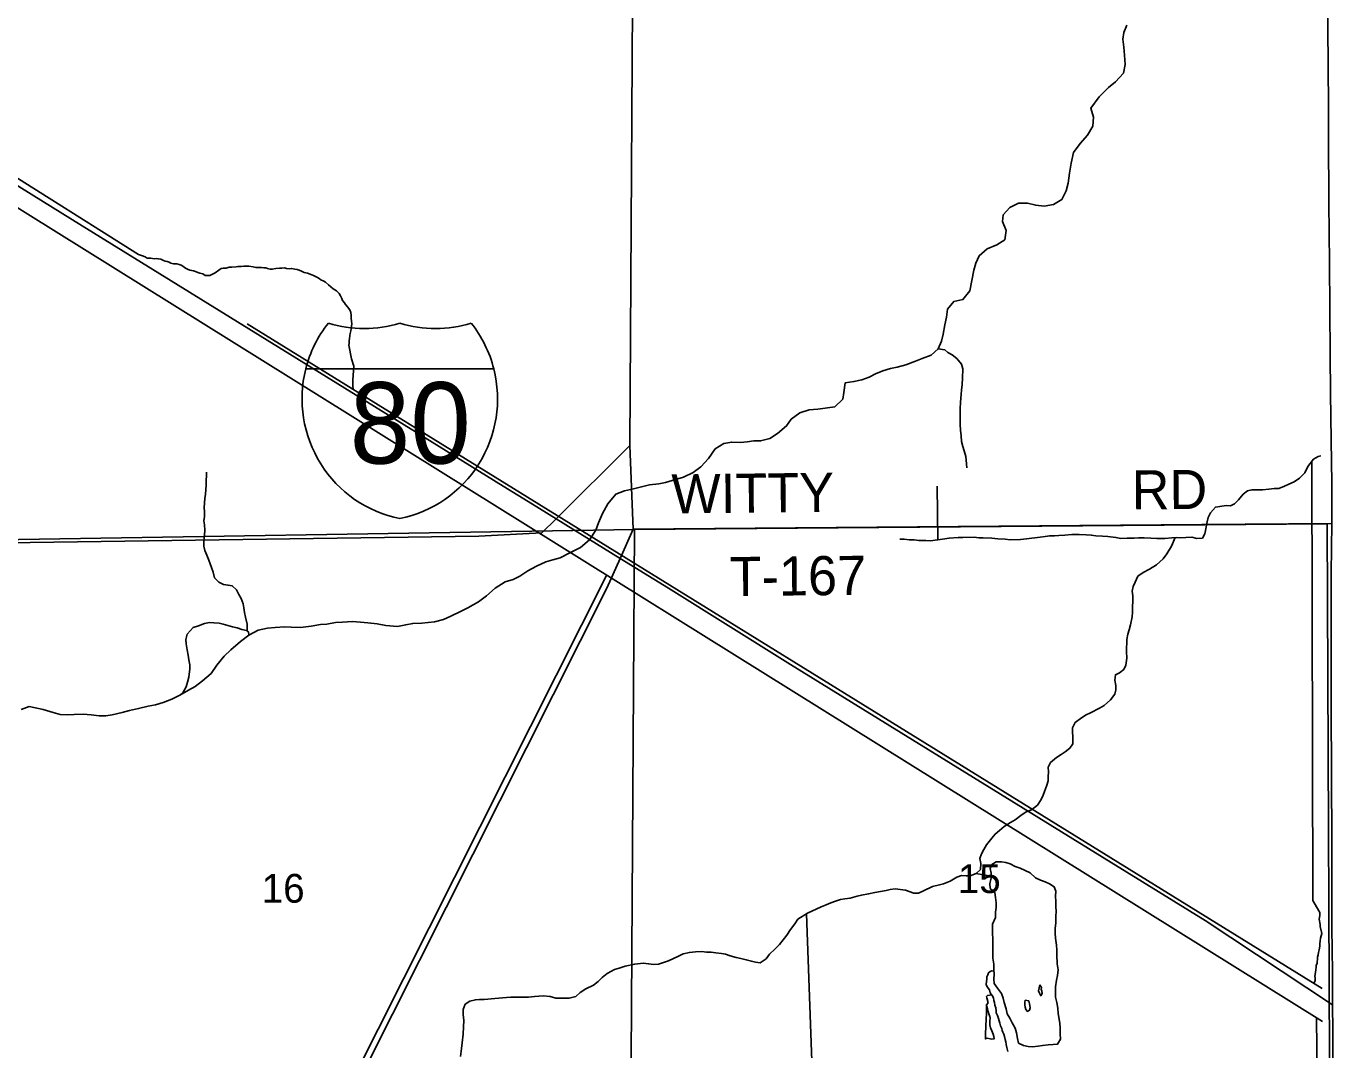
# Model space of a CAD drawing. Extents: x 1588073 to 2013523, y 1090242 to 1357120.
# Drawn here: x 1728558 to 1738590, y 1267246 to 1275104 of the extents above; entities that cross this region are included whole.
import ezdxf

# ---------------------------------------------------------------- set-up
doc = ezdxf.new("R2010")
doc.units = 0
for name, color, linetype in [('GM_X_Adjacent_County', 7, 'Continuous'), ('GM_X_County', 7, 'Continuous'), ('GM_X_County_Road', 7, 'Continuous'), ('GM_X_Interstate_Location', 7, 'Continuous'), ('GM_X_Interstate_Route', 7, 'Continuous'), ('GM_X_Interstate_Shield', 7, 'Continuous'), ('GM_X_Major_River', 7, 'Continuous'), ('GM_X_Minor_Lake', 7, 'Continuous'), ('GM_X_Minor_River', 7, 'Continuous'), ('GM_X_Section', 7, 'Continuous'), ('GM_X_Section_Text', 7, 'Continuous'), ('GM_X_Township', 7, 'Continuous'), ('GM_X_Township_Road', 7, 'Continuous'), ('GM_X_Township_Road_Text', 7, 'Continuous')]:
    doc.layers.add(name, color=color, linetype=linetype)

msp = doc.modelspace()

# ---------------------------------------------------------------- linework, layer by layer
at = {"layer": 'GM_X_Adjacent_County'}
msp.add_lwpolyline([(1738550, 1275274), (1738551, 1275094), (1738555, 1274798), (1738556, 1274485), (1738557, 1274256), (1738559, 1273747), (1738563, 1273288), (1738570, 1272581), (1738571, 1272286), (1738576, 1271925), (1738583, 1271596), (1738583, 1271286), (1738578, 1270907), (1738576, 1270281), (1738577, 1269874), (1738581, 1268839), (1738583, 1268494), (1738583, 1268182), (1738587, 1267846), (1738587, 1267761), (1738587, 1267676), (1738587, 1267593), (1738589, 1267394), (1738590, 1267179)], dxfattribs=at)
at = {"layer": 'GM_X_County'}
msp.add_lwpolyline([(1738550, 1275274), (1738551, 1275094), (1738555, 1274798), (1738556, 1274485), (1738557, 1274256), (1738559, 1273747), (1738563, 1273288), (1738570, 1272581), (1738571, 1272286), (1738576, 1271925), (1738583, 1271596), (1738583, 1271286), (1738578, 1270907), (1738576, 1270281), (1738577, 1269874), (1738581, 1268839), (1738583, 1268494), (1738583, 1268182), (1738587, 1267846), (1738587, 1267761), (1738587, 1267676), (1738587, 1267593), (1738589, 1267394), (1738590, 1267179)], dxfattribs=at)
at = {"layer": 'GM_X_County_Road'}
for points in [[(1738583, 1271286), (1738583, 1271596), (1738576, 1271925), (1738571, 1272286), (1738570, 1272581), (1738563, 1273288), (1738559, 1273747), (1738557, 1274256), (1738556, 1274485), (1738555, 1274798), (1738551, 1275094), (1738550, 1275274), (1738545, 1275652), (1738544, 1275816), (1738542, 1275964), (1738541, 1276144), (1738537, 1276358), (1738534, 1276572), (1738534, 1276592)], [(1730572, 1262010), (1730565, 1263302), (1730549, 1265887), (1733017, 1270791), (1733118, 1271018), (1733219, 1271243), (1733193, 1271885), (1733222, 1276540)], [(1738590, 1267179), (1738589, 1267394), (1738587, 1267593), (1738587, 1267676), (1738587, 1267761), (1738587, 1267846), (1738583, 1268182), (1738583, 1268494), (1738581, 1268839), (1738577, 1269874), (1738576, 1270281), (1738578, 1270907), (1738583, 1271286)]]:
    msp.add_lwpolyline(points, dxfattribs=at)
at = {"layer": 'GM_X_Interstate_Route'}
msp.add_lwpolyline([(1724225, 1276479), (1725529, 1275710), (1726922, 1274850), (1727192, 1274684), (1727551, 1274461), (1727819, 1274295), (1727885, 1274253), (1728987, 1273572), (1731547, 1271991), (1732220, 1271572), (1732446, 1271435), (1732627, 1271323), (1733118, 1271018), (1733490, 1270790), (1734426, 1270205), (1736889, 1268684), (1737609, 1268240), (1738587, 1267593)], dxfattribs=at)
at = {"layer": 'GM_X_Interstate_Shield'}
for p, q in [((1730706, 1272473), (1732148, 1272473)), ((1732148, 1272473), (1730706, 1272473)), ((1732148, 1272473), (1730706, 1272473))]:
    msp.add_line(p, q, dxfattribs=at)
for centre, start, end in [((1731614, 1272243), 141.669, 165.8066), ((1731153, 1273721), 253.0091, 286.9909), ((1731701, 1273721), 253.0091, 286.9909), ((1731239, 1272243), 14.1934, 38.331), ((1731614, 1272243), 165.8066, 258.463), ((1731239, 1272243), 281.537, 14.1934)]:
    msp.add_arc(centre, 938, start, end, dxfattribs=at)
at = {"layer": 'GM_X_Major_River'}
for points in [[(1737009, 1275112), (1736984, 1275054), (1736978, 1275004), (1736984, 1274942), (1736991, 1274882), (1736995, 1274810), (1736982, 1274742), (1736920, 1274676), (1736868, 1274634), (1736797, 1274560), (1736732, 1274474), (1736752, 1274404), (1736746, 1274336), (1736705, 1274268), (1736649, 1274202), (1736598, 1274133), (1736580, 1274052), (1736567, 1273974), (1736557, 1273898), (1736542, 1273840), (1736510, 1273772), (1736445, 1273735), (1736373, 1273723), (1736309, 1273729), (1736245, 1273746), (1736177, 1273746), (1736111, 1273712), (1736058, 1273655), (1736054, 1273605), (1736082, 1273534), (1736071, 1273464), (1736011, 1273424), (1735937, 1273395), (1735874, 1273341), (1735850, 1273285), (1735833, 1273231), (1735819, 1273151), (1735802, 1273073), (1735750, 1273005), (1735680, 1272989), (1735631, 1272932), (1735625, 1272869), (1735610, 1272811), (1735598, 1272739), (1735586, 1272687), (1735559, 1272627), (1735505, 1272578), (1735437, 1272554), (1735386, 1272532), (1735312, 1272505), (1735246, 1272487), (1735194, 1272475), (1735136, 1272457), (1735079, 1272434), (1735029, 1272410), (1734975, 1272388), (1734913, 1272375), (1734847, 1272367), (1734836, 1272293), (1734828, 1272241), (1734767, 1272183), (1734637, 1272164), (1734569, 1272158), (1734499, 1272137), (1734432, 1272087), (1734396, 1272035), (1734327, 1271977), (1734267, 1271939), (1734197, 1271920), (1734145, 1271920), (1734093, 1271914), (1734043, 1271907), (1733975, 1271911), (1733914, 1271900), (1733848, 1271860), (1733797, 1271786), (1733737, 1271722), (1733679, 1271678), (1733604, 1271641), (1733544, 1271623)], [(1733544, 1271623), (1733466, 1271600), (1733414, 1271592), (1733344, 1271582), (1733293, 1271570), (1733221, 1271553), (1733151, 1271537), (1733085, 1271512), (1733024, 1271438), (1732982, 1271362), (1732953, 1271292), (1732931, 1271236), (1732882, 1271162), (1732814, 1271102), (1732733, 1271061), (1732657, 1271023), (1732601, 1271007), (1732547, 1270992), (1732476, 1270960), (1732410, 1270924), (1732348, 1270883), (1732296, 1270857), (1732235, 1270839), (1732159, 1270789), (1732093, 1270730), (1732030, 1270686), (1731950, 1270640), (1731898, 1270613), (1731819, 1270575), (1731761, 1270549), (1731693, 1270532), (1731597, 1270522), (1731526, 1270519), (1731472, 1270509), (1731410, 1270497), (1731320, 1270504), (1731254, 1270516), (1731180, 1270525), (1731126, 1270529), (1731064, 1270533), (1730986, 1270530), (1730932, 1270526), (1730867, 1270515), (1730817, 1270511), (1730747, 1270499), (1730665, 1270488), (1730593, 1270492), (1730543, 1270494), (1730471, 1270489), (1730411, 1270483), (1730338, 1270468), (1730268, 1270430), (1730204, 1270380), (1730129, 1270318), (1730079, 1270267), (1730022, 1270199), (1729978, 1270135), (1729913, 1270079), (1729855, 1270035), (1729805, 1270006), (1729739, 1269970), (1729676, 1269938), (1729610, 1269913), (1729550, 1269895), (1729496, 1269885), (1729421, 1269866), (1729351, 1269850), (1729295, 1269836), (1729219, 1269819), (1729169, 1269811), (1729119, 1269811), (1729057, 1269818), (1728997, 1269822), (1728926, 1269820), (1728876, 1269817), (1728820, 1269821), (1728766, 1269835), (1728688, 1269858), (1728581, 1269881)], [(1728581, 1269881), (1728521, 1269860)], [(1736331, 1267699), (1736337, 1267682), (1736347, 1267662), (1736357, 1267680), (1736355, 1267698), (1736351, 1267712), (1736352, 1267726), (1736340, 1267746)], [(1736340, 1267746), (1736331, 1267699)], [(1736228, 1267627), (1736226, 1267612), (1736225, 1267593), (1736227, 1267575), (1736233, 1267557), (1736245, 1267541), (1736261, 1267551), (1736265, 1267569), (1736263, 1267587), (1736256, 1267623)], [(1736256, 1267623), (1736228, 1267627)]]:
    msp.add_lwpolyline(points, dxfattribs=at)
at = {"layer": 'GM_X_Minor_Lake'}
for points in [[(1735972, 1268669), (1735959, 1268638), (1735966, 1268603), (1735967, 1268565), (1735957, 1268523), (1735960, 1268485), (1735994, 1268455), (1736001, 1268416), (1736005, 1268376), (1736004, 1268340), (1736000, 1268304), (1735999, 1268262), (1735978, 1268210), (1735977, 1268138), (1735979, 1268102), (1735980, 1268038), (1735979, 1267994), (1735980, 1267950), (1735988, 1267904), (1735987, 1267862), (1735989, 1267825), (1735988, 1267791), (1735990, 1267755), (1736015, 1267721), (1736046, 1267678), (1736060, 1267644), (1736067, 1267610), (1736081, 1267562), (1736090, 1267523), (1736110, 1267489), (1736127, 1267453), (1736151, 1267412), (1736162, 1267376), (1736169, 1267334), (1736177, 1267298), (1736215, 1267279), (1736251, 1267272), (1736285, 1267270), (1736327, 1267275), (1736361, 1267279), (1736405, 1267284), (1736443, 1267288), (1736477, 1267291), (1736498, 1267329), (1736496, 1267369), (1736497, 1267415), (1736494, 1267449), (1736488, 1267483), (1736481, 1267526), (1736479, 1267566), (1736470, 1267610), (1736461, 1267650), (1736461, 1267690), (1736460, 1267730), (1736468, 1267782), (1736477, 1267818), (1736480, 1267860), (1736474, 1267908), (1736471, 1267977), (1736470, 1268015), (1736468, 1268051), (1736461, 1268103), (1736458, 1268141), (1736458, 1268179), (1736463, 1268221), (1736464, 1268273), (1736466, 1268309), (1736463, 1268348), (1736463, 1268384), (1736460, 1268426), (1736463, 1268464), (1736451, 1268498), (1736415, 1268521), (1736382, 1268535), (1736346, 1268550), (1736306, 1268566), (1736266, 1268605), (1736227, 1268624), (1736189, 1268640), (1736151, 1268653), (1736113, 1268673), (1736079, 1268684), (1736047, 1268690)], [(1736047, 1268690), (1736043, 1268690), (1736005, 1268689), (1735972, 1268669)], [(1735931, 1267594), (1735930, 1267542), (1735930, 1267512), (1735928, 1267496), (1735927, 1267462), (1735925, 1267448), (1735923, 1267345), (1735923, 1267331), (1735937, 1267335), (1735959, 1267331), (1735973, 1267329), (1735989, 1267330), (1735987, 1267348)], [(1735931, 1267594), (1735930, 1267542), (1735930, 1267512), (1735928, 1267496), (1735927, 1267462), (1735925, 1267448), (1735923, 1267345), (1735923, 1267331), (1735937, 1267335), (1735959, 1267331), (1735973, 1267329), (1735989, 1267330), (1735987, 1267348), (1735982, 1267367), (1735972, 1267393), (1735962, 1267415), (1735957, 1267439), (1735957, 1267469), (1735960, 1267489), (1735956, 1267503), (1735950, 1267523), (1735944, 1267542), (1735939, 1267562), (1735933, 1267580), (1735931, 1267594)], [(1735987, 1267348), (1735982, 1267367), (1735972, 1267393), (1735962, 1267415), (1735957, 1267439), (1735957, 1267469), (1735960, 1267489), (1735956, 1267503), (1735950, 1267523), (1735944, 1267542), (1735939, 1267562), (1735933, 1267580), (1735931, 1267594)]]:
    msp.add_lwpolyline(points, dxfattribs=at)
at = {"layer": 'GM_X_Minor_River'}
for p, q in [((1724253, 1276352), (1738510, 1267465)), ((1724641, 1276356), (1729421, 1273352)), ((1730256, 1272820), (1738508, 1267717)), ((1738428, 1271763), (1738437, 1268394)), ((1735552, 1271572), (1735558, 1271162)), ((1733015, 1270892), (1730501, 1265898)), ((1735848, 1268600), (1735966, 1268579)), ((1734549, 1268291), (1734632, 1265984)), ((1738448, 1267755), (1738448, 1267755)), ((1735932, 1267657), (1735939, 1267663)), ((1735933, 1267647), (1735932, 1267657)), ((1735932, 1267657), (1735932, 1267657)), ((1735939, 1267663), (1735971, 1267668)), ((1735939, 1267663), (1735939, 1267663)), ((1735931, 1267591), (1735943, 1267607)), ((1735943, 1267607), (1735933, 1267647)), ((1735933, 1267647), (1735933, 1267647)), ((1735943, 1267607), (1735943, 1267607)), ((1738464, 1267494), (1738525, 1261851))]:
    msp.add_line(p, q, dxfattribs=at)
for points in [[(1729421, 1273352), (1729452, 1273341), (1729472, 1273332), (1729486, 1273324), (1729500, 1273324), (1729514, 1273322), (1729540, 1273319), (1729556, 1273321), (1729574, 1273317), (1729592, 1273315), (1729612, 1273306), (1729626, 1273300), (1729640, 1273298), (1729656, 1273292), (1729670, 1273285), (1729690, 1273279), (1729716, 1273279), (1729732, 1273274), (1729748, 1273268), (1729762, 1273262), (1729781, 1273246), (1729797, 1273239), (1729815, 1273231), (1729829, 1273227), (1729843, 1273225), (1729859, 1273220), (1729877, 1273214), (1729891, 1273208), (1729915, 1273202), (1729933, 1273191), (1729953, 1273189), (1729969, 1273189), (1729993, 1273202), (1730009, 1273210), (1730037, 1273230), (1730054, 1273244), (1730070, 1273245), (1730094, 1273247), (1730116, 1273253), (1730136, 1273254), (1730170, 1273256), (1730184, 1273258), (1730210, 1273259), (1730230, 1273261), (1730250, 1273261), (1730268, 1273261), (1730300, 1273256), (1730322, 1273252), (1730366, 1273251), (1730384, 1273249), (1730398, 1273249), (1730412, 1273244), (1730432, 1273238), (1730448, 1273238), (1730474, 1273243), (1730502, 1273247), (1730522, 1273247), (1730542, 1273248), (1730556, 1273244), (1730578, 1273242), (1730596, 1273244), (1730620, 1273239), (1730638, 1273235), (1730654, 1273231), (1730672, 1273223), (1730692, 1273214), (1730718, 1273208), (1730750, 1273195), (1730764, 1273189), (1730780, 1273181), (1730794, 1273175), (1730807, 1273166), (1730821, 1273156), (1730843, 1273146), (1730857, 1273138), (1730879, 1273117), (1730914, 1273087), (1730940, 1273072), (1730960, 1273052), (1730972, 1273034), (1730981, 1273014), (1730987, 1272999), (1731003, 1272981), (1731011, 1272967), (1731025, 1272949), (1731042, 1272926), (1731050, 1272906), (1731052, 1272882), (1731053, 1272862), (1731057, 1272840), (1731059, 1272818), (1731056, 1272800), (1731052, 1272780), (1731050, 1272766), (1731046, 1272744), (1731043, 1272730), (1731041, 1272704), (1731039, 1272690), (1731038, 1272668), (1731036, 1272654), (1731055, 1272551)], [(1735559, 1272627), (1735610, 1272619), (1735633, 1272600), (1735667, 1272582), (1735703, 1272553), (1735738, 1272509), (1735748, 1272473), (1735747, 1272401), (1735745, 1272354), (1735740, 1272310), (1735736, 1272278), (1735731, 1272214), (1735729, 1272170), (1735728, 1272112), (1735728, 1272078), (1735729, 1272046), (1735731, 1272002), (1735737, 1271958), (1735740, 1271916), (1735748, 1271877), (1735759, 1271845), (1735771, 1271801), (1735778, 1271745), (1735780, 1271713)], [(1731055, 1272551), (1731074, 1272493), (1731066, 1272389), (1731066, 1272336), (1731072, 1272315)], [(1738498, 1271805), (1738477, 1271801), (1738441, 1271780), (1738398, 1271724), (1738374, 1271674), (1738333, 1271634), (1738293, 1271607), (1738253, 1271587), (1738218, 1271573), (1738176, 1271556), (1738140, 1271554), (1738098, 1271551), (1738050, 1271545), (1738006, 1271544), (1737968, 1271544), (1737934, 1271536), (1737902, 1271511), (1737865, 1271469), (1737835, 1271437), (1737803, 1271423), (1737771, 1271424), (1737722, 1271418), (1737688, 1271413), (1737650, 1271367), (1737632, 1271333), (1737625, 1271299), (1737606, 1271207), (1737588, 1271173), (1737546, 1271170), (1737508, 1271182), (1737460, 1271180), (1737424, 1271177), (1737388, 1271179), (1737354, 1271177), (1737300, 1271170), (1737238, 1271171), (1737192, 1271173), (1737140, 1271176), (1737099, 1271176), (1737065, 1271174), (1737011, 1271173), (1736963, 1271171), (1736925, 1271180), (1736863, 1271187), (1736821, 1271189), (1736769, 1271192), (1736735, 1271198), (1736695, 1271200), (1736641, 1271203), (1736585, 1271201), (1736533, 1271198), (1736487, 1271194), (1736453, 1271193), (1736417, 1271193), (1736381, 1271187), (1736343, 1271182), (1736239, 1271169), (1736191, 1271163), (1736113, 1271162), (1736075, 1271165), (1736017, 1271169), (1735971, 1271174), (1735905, 1271176), (1735873, 1271177), (1735835, 1271181), (1735748, 1271180), (1735714, 1271178), (1735644, 1271175), (1735592, 1271165), (1735502, 1271154), (1735464, 1271157), (1735412, 1271157), (1735376, 1271162), (1735338, 1271162), (1735300, 1271166), (1735266, 1271165)], [(1730256, 1270463), (1730255, 1270513), (1730242, 1270567), (1730234, 1270603), (1730229, 1270639), (1730225, 1270671), (1730209, 1270710), (1730192, 1270742), (1730174, 1270778), (1730140, 1270808), (1730108, 1270813), (1730074, 1270819), (1730037, 1270836), (1730005, 1270870), (1729993, 1270914), (1729982, 1270948), (1729960, 1271005), (1729945, 1271043), (1729929, 1271079), (1729921, 1271113), (1729922, 1271155), (1729926, 1271197), (1729931, 1271234), (1729927, 1271276), (1729923, 1271308), (1729926, 1271340), (1729928, 1271376), (1729924, 1271410), (1729929, 1271478), (1729936, 1271512), (1729938, 1271546), (1729940, 1271582), (1729941, 1271618), (1729943, 1271652), (1729943, 1271681)], [(1737379, 1271179), (1737351, 1271113), (1737314, 1271054), (1737288, 1271016), (1737237, 1270970), (1737181, 1270935), (1737133, 1270911), (1737092, 1270882), (1737072, 1270836), (1737056, 1270802), (1737049, 1270768), (1737053, 1270732), (1737052, 1270607), (1737049, 1270569), (1737037, 1270509), (1737026, 1270469), (1737016, 1270437), (1737007, 1270397), (1737006, 1270305), (1737008, 1270253), (1737001, 1270199), (1736985, 1270165), (1736953, 1270141), (1736920, 1270126), (1736916, 1270084), (1736924, 1270043), (1736925, 1270011), (1736917, 1269977), (1736882, 1269934), (1736834, 1269890), (1736798, 1269870), (1736729, 1269833), (1736695, 1269817), (1736659, 1269796), (1736612, 1269760), (1736590, 1269718), (1736592, 1269684), (1736593, 1269652), (1736593, 1269596), (1736570, 1269562), (1736536, 1269534), (1736504, 1269513), (1736468, 1269491), (1736423, 1269451), (1736405, 1269417), (1736406, 1269381), (1736404, 1269343), (1736404, 1269311), (1736395, 1269277), (1736366, 1269201), (1736350, 1269167), (1736322, 1269124), (1736277, 1269088), (1736235, 1269074), (1736195, 1269045), (1736152, 1269013), (1736114, 1268991), (1736066, 1268960), (1736031, 1268930), (1735997, 1268902), (1735971, 1268871), (1735930, 1268821), (1735910, 1268785), (1735893, 1268751), (1735879, 1268715), (1735887, 1268677), (1735884, 1268631), (1735852, 1268601), (1735806, 1268582), (1735774, 1268582), (1735738, 1268586), (1735703, 1268573), (1735651, 1268541), (1735601, 1268522), (1735569, 1268512), (1735515, 1268501), (1735448, 1268467), (1735410, 1268450), (1735374, 1268448), (1735308, 1268471), (1735230, 1268483), (1735192, 1268478), (1735160, 1268470), (1735074, 1268455), (1735026, 1268443), (1734971, 1268434), (1734939, 1268426), (1734883, 1268411), (1734843, 1268405), (1734811, 1268400), (1734771, 1268388), (1734737, 1268374), (1734701, 1268359), (1734662, 1268345), (1734556, 1268296), (1734483, 1268249), (1734459, 1268213), (1734426, 1268169), (1734398, 1268127), (1734341, 1268056), (1734309, 1268022)], [(1729739, 1269970), (1729764, 1269993), (1729786, 1270032), (1729797, 1270068), (1729807, 1270106), (1729814, 1270170), (1729814, 1270202), (1729808, 1270239), (1729801, 1270275), (1729795, 1270317), (1729786, 1270363), (1729784, 1270397), (1729794, 1270437), (1729841, 1270487), (1729881, 1270502), (1729927, 1270520), (1729965, 1270526), (1729999, 1270525), (1730039, 1270521), (1730071, 1270513), (1730107, 1270504), (1730143, 1270494), (1730179, 1270485), (1730215, 1270473), (1730249, 1270465), (1730264, 1270454), (1730268, 1270430)], [(1738445, 1267757), (1738453, 1267779), (1738453, 1267799), (1738451, 1267813), (1738456, 1267841), (1738460, 1267863), (1738462, 1267879), (1738463, 1267893), (1738469, 1267911), (1738469, 1267925), (1738471, 1267939), (1738473, 1267957), (1738476, 1267977), (1738480, 1267995), (1738484, 1268015), (1738489, 1268043), (1738491, 1268061), (1738493, 1268083), (1738494, 1268105), (1738500, 1268121), (1738504, 1268139), (1738493, 1268193), (1738493, 1268209), (1738486, 1268250), (1738490, 1268278), (1738491, 1268300), (1738483, 1268314), (1738437, 1268394)], [(1734309, 1268022), (1734266, 1267980), (1734238, 1267946), (1734192, 1267915), (1734158, 1267919), (1734126, 1267926), (1734086, 1267938), (1734044, 1267948), (1734010, 1267955), (1733962, 1267969), (1733928, 1267980), (1733896, 1267986), (1733854, 1267990), (1733816, 1267997), (1733780, 1267997), (1733746, 1268002), (1733696, 1268000), (1733650, 1267995), (1733602, 1267983), (1733566, 1267965), (1733489, 1267930), (1733413, 1267905), (1733377, 1267901), (1733337, 1267908), (1733295, 1267912), (1733231, 1267905), (1733158, 1267889), (1733110, 1267874), (1733074, 1267864), (1733018, 1267833), (1732979, 1267803), (1732949, 1267771), (1732913, 1267744), (1732856, 1267716), (1732812, 1267686), (1732778, 1267657), (1732726, 1267643), (1732668, 1267642), (1732624, 1267642), (1732580, 1267655), (1732526, 1267661), (1732460, 1267656), (1732415, 1267650), (1732337, 1267651), (1732279, 1267652), (1732245, 1267648), (1732155, 1267641), (1732075, 1267632), (1732039, 1267632), (1732007, 1267631), (1731965, 1267619), (1731929, 1267597), (1731914, 1267557), (1731912, 1267517), (1731917, 1267471), (1731915, 1267423), (1731912, 1267367), (1731905, 1267301), (1731901, 1267257), (1731892, 1267195)], [(1735991, 1267849), (1735973, 1267852), (1735959, 1267848), (1735945, 1267838), (1735940, 1267822), (1735934, 1267806), (1735934, 1267790), (1735930, 1267772), (1735927, 1267748), (1735937, 1267730), (1735953, 1267706), (1735960, 1267684), (1735974, 1267663), (1735984, 1267647), (1735986, 1267625), (1735991, 1267609), (1735995, 1267589), (1736003, 1267569), (1736004, 1267545), (1736006, 1267531), (1736016, 1267510), (1736022, 1267486), (1736027, 1267470), (1736033, 1267452), (1736039, 1267430), (1736048, 1267410), (1736050, 1267396), (1736056, 1267382), (1736064, 1267367), (1736070, 1267349), (1736073, 1267325), (1736079, 1267307), (1736081, 1267287), (1736086, 1267265), (1736094, 1267233)]]:
    msp.add_lwpolyline(points, dxfattribs=at)
at = {"layer": 'GM_X_Section'}
for points in [[(1733228, 1271241), (1738545, 1271283), (1738568, 1266014), (1733195, 1265968)], [(1727871, 1271153), (1733228, 1271241), (1733195, 1265968), (1727860, 1265868)]]:
    msp.add_lwpolyline(points, close=True, dxfattribs=at)
at = {"layer": 'GM_X_Township'}
msp.add_lwpolyline([(1738550, 1275274), (1738551, 1275094), (1738555, 1274798), (1738556, 1274485), (1738557, 1274256), (1738559, 1273747), (1738563, 1273288), (1738570, 1272581), (1738571, 1272286), (1738576, 1271925), (1738583, 1271596), (1738583, 1271286), (1738578, 1270907), (1738576, 1270281), (1738577, 1269874), (1738581, 1268839), (1738583, 1268494), (1738583, 1268182), (1738587, 1267846), (1738587, 1267761), (1738587, 1267676), (1738587, 1267593), (1738589, 1267394), (1738590, 1267179)], dxfattribs=at)
at = {"layer": 'GM_X_Township_Road'}
for points in [[(1727861, 1271130), (1732033, 1271190), (1732517, 1271214), (1732627, 1271323), (1733193, 1271885)], [(1733219, 1271243), (1737584, 1271278)], [(1737584, 1271278), (1738583, 1271286)]]:
    msp.add_lwpolyline(points, dxfattribs=at)

# ---------------------------------------------------------------- texts
at = {"layer": 'GM_X_Interstate_Location'}
for s in ['.', '-', ',']:
    msp.add_text(s, height=1, dxfattribs=at).set_placement((1731427, 1272074))
msp.add_text('80', height=1, rotation=0, dxfattribs=at).set_placement((1731223, 1271867))
at = {"layer": 'GM_X_Interstate_Shield'}
msp.add_text('80', height=625, dxfattribs=at).set_placement((1731042, 1271746))
at = {"layer": 'GM_X_Section_Text'}
for s, p in [('15', (1735711, 1268450)), ('16', (1730367, 1268376))]:
    msp.add_text(s, height=221, rotation=0, dxfattribs=at).set_placement(p)
at = {"layer": 'GM_X_Township_Road_Text'}
for s, rotation, p in [('WITTY', 0.641, (1733514, 1271363)), ('RD', 0.4937, (1737047, 1271394)), ('T-167', 0.5614, (1733960, 1270729))]:
    msp.add_text(s, height=300, rotation=rotation, dxfattribs=at).set_placement(p)

doc.saveas('drawing.dxf')
